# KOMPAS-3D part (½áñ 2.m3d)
File: created 10.02.2016 11:24:24, last saved 22.07.2016 16:32:08.
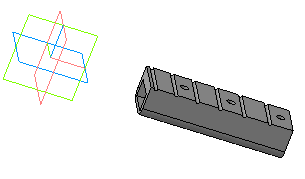
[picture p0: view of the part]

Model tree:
1. Эскиз:1
2. Операция выдавливания:1
     Расстояние 1 = 8
3. Эскиз:2
4. Операция выдавливания:2
     Расстояние 1 = 15.5
5. Вырезать элемент выдавливания:1
     Расстояние 1 = 320
6. Скругление:1
     Радиус = 7
7. Эскиз:3
8. Вырезать элемент выдавливания:2
     Расстояние 1 = 20
9. Эскиз:4
10. Вырезать элемент выдавливания:3
     Расстояние 2 = 40; Расстояние 1 = 65
11. Эскиз:5
12. Вырезать элемент выдавливания:4
     Расстояние 2 = 40; Расстояние 1 = 2
13. Эскиз:7
14. Вырезать элемент выдавливания:5
     Расстояние 1 = 40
